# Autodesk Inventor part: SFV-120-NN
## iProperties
Created: 2006-07
Part Number: SFV-120-NN
Material: 1.4301 X5CrNi10-10 A2
Document SubType Name: Modellieren
Designer: TMT
Manufacturer: Standard
Standards Organization: Custom
Description: Drehdurchführung  DN40 ISO-KF
Author: TMT
Comments: FERROFLUIDICS
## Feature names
1. Extrusion2
2. Extrusion3
3. Extrusion4
4. Extrusion5
5. Extrusion6
6. Fase1 [Chamfer]
7. Fase2 [Chamfer]
8. Extrusion7
9. Extrusion8
10. Fase3 [Chamfer]
11. Extrusion9
12. Rundung3 [Fillet]
